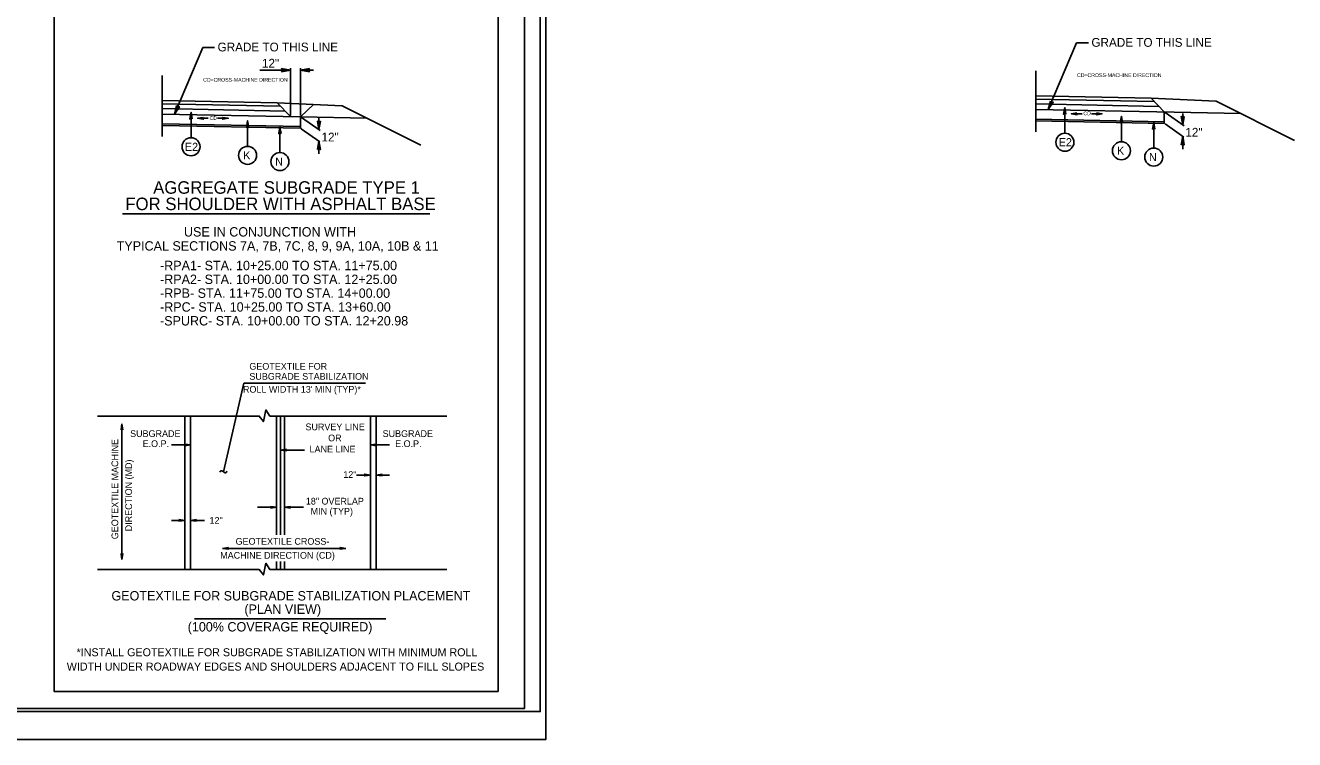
# Model space of a CAD drawing. Extents: x 573748 to 574632, y -54663 to -53209.
# Drawn here: x 574197.7 to 574400.7, y -54603.6 to -54489.5 of the extents above; entities that cross this region are included whole.
import ezdxf

# ---------------------------------------------------------------- set-up
doc = ezdxf.new("R2010")
doc.units = 0
for name, color, linetype in [('Prop Dimension', 7, 'Continuous'), ('Prop Dimension Text', 7, 'Continuous'), ('Prop Terminator CELL', 7, 'Continuous'), ('Sheet Cutting Line CELL', 7, 'Continuous'), ('Sheet Plot Border Inside CELL', 7, 'Continuous'), ('Sheet Plot Border Outside CELL', 7, 'Continuous'), ('Sheet Typical CELL', 7, 'Continuous'), ('Typical Hinge Slope Interstate CELL', 7, 'Continuous'), ('Typical ID Circle CELL', 7, 'Continuous'), ('Typical Pavement Slope CELL', 7, 'Continuous'), ('Typical Shoulder Slope CELL', 7, 'Continuous'), ('Typical Terminator CELL', 7, 'Continuous'), ('Typical Text General CELL', 7, 'Continuous'), ('Typical Text ID Circle CELL', 7, 'Continuous')]:
    doc.layers.add(name, color=color, linetype=linetype)

msp = doc.modelspace()

# ---------------------------------------------------------------- linework, layer by layer
at = {"layer": 'Prop Dimension'}
for p, q in [((574226.11, -54492.97), (574221.58, -54503.66)), ((574226.11, -54492.97), (574228, -54492.97)), ((574365.85, -54492.23), (574361.32, -54502.92)), ((574365.85, -54492.23), (574367.74, -54492.23)), ((574219.59, -54507.2), (574219.59, -54497.44)), ((574359.33, -54506.46), (574359.33, -54496.7)), ((574366.72, -54503.58), (574365.01, -54503.58)), ((574368.22, -54503.58), (574369.92, -54503.58)), ((574226.98, -54504.31), (574225.27, -54504.31)), ((574228.48, -54504.31), (574230.19, -54504.31)), ((574213.27, -54519.6), (574262.41, -54519.6))]:
    msp.add_line(p, q, dxfattribs=at)
msp.add_lwpolyline([(574202.34, -54435.95), (574273.34, -54435.95), (574273.34, -54595.94), (574202.34, -54595.94)], close=True, dxfattribs=at)
at = {"layer": 'Prop Dimension Text'}
for p, q in [((574235.21, -54496.62), (574240.14, -54496.62)), ((574240.14, -54503.87), (574240.14, -54496.3)), ((574241.74, -54503.87), (574241.74, -54496.3)), ((574241.74, -54496.62), (574243.8, -54496.62)), ((574380.02, -54503.4), (574383.03, -54505.51)), ((574382.82, -54505.36), (574382.82, -54503.54)), ((574241.89, -54504.17), (574244.9, -54506.27)), ((574244.68, -54506.12), (574244.68, -54504.31)), ((574379.99, -54505.2), (574382.99, -54507.3)), ((574241.85, -54505.97), (574244.85, -54508.07)), ((574382.82, -54509.24), (574382.82, -54507.18)), ((574244.68, -54510.01), (574244.68, -54507.95)), ((574229.41, -54560.83), (574232.67, -54546.68)), ((574232.67, -54546.68), (574252.15, -54546.68)), ((574223.23, -54551.93), (574223.23, -54576.45)), ((574224.15, -54551.93), (574224.15, -54576.45)), ((574237.89, -54570.9), (574237.89, -54551.93)), ((574238.53, -54570.9), (574238.53, -54551.93)), ((574239.17, -54570.9), (574239.17, -54551.93)), ((574252.91, -54551.93), (574252.91, -54576.45)), ((574253.83, -54551.93), (574253.83, -54576.45)), ((574213.19, -54553.15), (574213.05, -54554.12)), ((574213.05, -54554.12), (574213.19, -54554)), ((574213.07, -54554.1), (574213.19, -54553.15)), ((574213.19, -54553.15), (574213.09, -54554.08)), ((574213.11, -54554.07), (574213.19, -54553.15)), ((574213.19, -54553.15), (574213.13, -54554.05)), ((574213.15, -54554.03), (574213.19, -54553.15)), ((574213.19, -54553.15), (574213.17, -54554.01)), ((574213.19, -54553.15), (574213.32, -54554.12)), ((574213.19, -54554), (574213.19, -54553.15)), ((574213.2, -54554.01), (574213.19, -54553.15)), ((574213.19, -54553.15), (574213.22, -54554.03)), ((574213.24, -54554.05), (574213.19, -54553.15)), ((574213.19, -54553.15), (574213.26, -54554.07)), ((574213.28, -54554.08), (574213.19, -54553.15)), ((574213.19, -54553.15), (574213.3, -54554.1)), ((574213.19, -54574.87), (574213.19, -54553.15)), ((574213.19, -54554), (574213.32, -54554.12)), ((574221.1, -54556.52), (574224.15, -54556.52)), ((574224.15, -54556.52), (574223.18, -54556.39)), ((574223.18, -54556.39), (574223.31, -54556.52)), ((574224.15, -54556.52), (574223.18, -54556.65)), ((574223.31, -54556.52), (574223.18, -54556.65)), ((574223.2, -54556.4), (574224.15, -54556.52)), ((574224.15, -54556.52), (574223.2, -54556.63)), ((574224.15, -54556.52), (574223.22, -54556.42)), ((574223.22, -54556.61), (574224.15, -54556.52)), ((574223.23, -54556.44), (574224.15, -54556.52)), ((574224.15, -54556.52), (574223.23, -54556.59)), ((574224.15, -54556.52), (574223.25, -54556.46)), ((574223.25, -54556.57), (574224.15, -54556.52)), ((574223.27, -54556.48), (574224.15, -54556.52)), ((574224.15, -54556.52), (574223.27, -54556.55)), ((574224.15, -54556.52), (574223.29, -54556.5)), ((574223.29, -54556.54), (574224.15, -54556.52)), ((574223.31, -54556.52), (574224.15, -54556.52)), ((574252.91, -54556.52), (574253.88, -54556.39)), ((574253.87, -54556.4), (574252.91, -54556.52)), ((574252.91, -54556.52), (574253.85, -54556.42)), ((574253.83, -54556.44), (574252.91, -54556.52)), ((574252.91, -54556.52), (574253.81, -54556.46)), ((574253.79, -54556.48), (574252.91, -54556.52)), ((574252.91, -54556.52), (574253.78, -54556.5)), ((574255.96, -54556.52), (574252.91, -54556.52)), ((574252.91, -54556.52), (574253.88, -54556.65)), ((574253.76, -54556.52), (574252.91, -54556.52)), ((574253.78, -54556.54), (574252.91, -54556.52)), ((574252.91, -54556.52), (574253.79, -54556.55)), ((574253.81, -54556.57), (574252.91, -54556.52)), ((574252.91, -54556.52), (574253.83, -54556.59)), ((574253.85, -54556.61), (574252.91, -54556.52)), ((574252.91, -54556.52), (574253.87, -54556.63)), ((574253.88, -54556.39), (574253.76, -54556.52)), ((574253.76, -54556.52), (574253.88, -54556.65)), ((574238.53, -54557.36), (574239.5, -54557.23)), ((574238.53, -54557.36), (574239.48, -54557.25)), ((574239.46, -54557.26), (574238.53, -54557.36)), ((574238.53, -54557.36), (574239.45, -54557.28)), ((574239.43, -54557.3), (574238.53, -54557.36)), ((574238.53, -54557.36), (574239.41, -54557.32)), ((574239.39, -54557.34), (574238.53, -54557.36)), ((574238.53, -54557.36), (574239.5, -54557.49)), ((574239.48, -54557.47), (574238.53, -54557.36)), ((574238.53, -54557.36), (574239.46, -54557.45)), ((574239.45, -54557.43), (574238.53, -54557.36)), ((574238.53, -54557.36), (574239.43, -54557.41)), ((574239.41, -54557.4), (574238.53, -54557.36)), ((574238.53, -54557.36), (574239.39, -54557.38)), ((574239.38, -54557.36), (574238.53, -54557.36)), ((574238.53, -54557.36), (574242.38, -54557.36)), ((574239.38, -54557.36), (574239.5, -54557.23)), ((574239.5, -54557.49), (574239.38, -54557.36)), ((574228.82, -54560.89), (574228.87, -54560.8)), ((574229.24, -54560.71), (574229.58, -54560.95)), ((574229.91, -54560.87), (574229.97, -54560.75)), ((574252.91, -54561.34), (574250.67, -54561.34)), ((574252.91, -54561.34), (574251.94, -54561.21)), ((574252.07, -54561.34), (574251.94, -54561.21)), ((574252.91, -54561.34), (574251.94, -54561.47)), ((574251.94, -54561.47), (574252.07, -54561.34)), ((574252.91, -54561.34), (574251.96, -54561.23)), ((574251.96, -54561.45), (574252.91, -54561.34)), ((574251.98, -54561.25), (574252.91, -54561.34)), ((574252.91, -54561.34), (574251.98, -54561.44)), ((574252.91, -54561.34), (574252, -54561.27)), ((574252, -54561.42), (574252.91, -54561.34)), ((574252.02, -54561.29), (574252.91, -54561.34)), ((574252.91, -54561.34), (574252.02, -54561.4)), ((574252.91, -54561.34), (574252.03, -54561.31)), ((574252.03, -54561.38), (574252.91, -54561.34)), ((574252.05, -54561.32), (574252.91, -54561.34)), ((574252.91, -54561.34), (574252.05, -54561.36)), ((574252.07, -54561.34), (574252.91, -54561.34)), ((574253.83, -54561.34), (574254.8, -54561.21)), ((574254.78, -54561.23), (574253.83, -54561.34)), ((574253.83, -54561.34), (574254.76, -54561.25)), ((574254.74, -54561.27), (574253.83, -54561.34)), ((574253.83, -54561.34), (574254.73, -54561.29)), ((574254.71, -54561.3), (574253.83, -54561.34)), ((574253.83, -54561.34), (574254.69, -54561.32)), ((574255.96, -54561.34), (574253.83, -54561.34)), ((574253.83, -54561.34), (574254.8, -54561.47)), ((574254.67, -54561.34), (574253.83, -54561.34)), ((574254.69, -54561.36), (574253.83, -54561.34)), ((574253.83, -54561.34), (574254.71, -54561.38)), ((574254.73, -54561.4), (574253.83, -54561.34)), ((574253.83, -54561.34), (574254.74, -54561.42)), ((574254.76, -54561.44), (574253.83, -54561.34)), ((574253.83, -54561.34), (574254.78, -54561.45)), ((574254.8, -54561.21), (574254.67, -54561.34)), ((574254.67, -54561.34), (574254.8, -54561.47)), ((574234.87, -54566.5), (574237.89, -54566.5)), ((574237.89, -54566.5), (574236.92, -54566.37)), ((574236.92, -54566.37), (574237.05, -54566.5)), ((574237.89, -54566.5), (574236.92, -54566.63)), ((574237.05, -54566.5), (574236.92, -54566.63)), ((574236.94, -54566.39), (574237.89, -54566.5)), ((574237.89, -54566.5), (574236.94, -54566.61)), ((574237.89, -54566.5), (574236.96, -54566.41)), ((574236.96, -54566.59), (574237.89, -54566.5)), ((574236.98, -54566.43), (574237.89, -54566.5)), ((574237.89, -54566.5), (574236.98, -54566.58)), ((574237.89, -54566.5), (574236.99, -54566.45)), ((574236.99, -54566.56), (574237.89, -54566.5)), ((574237.01, -54566.46), (574237.89, -54566.5)), ((574237.89, -54566.5), (574237.01, -54566.54)), ((574237.89, -54566.5), (574237.03, -54566.48)), ((574237.03, -54566.52), (574237.89, -54566.5)), ((574237.05, -54566.5), (574237.89, -54566.5)), ((574239.17, -54566.5), (574240.14, -54566.37)), ((574239.17, -54566.5), (574240.12, -54566.39)), ((574240.1, -54566.41), (574239.17, -54566.5)), ((574239.17, -54566.5), (574240.09, -54566.43)), ((574240.07, -54566.45), (574239.17, -54566.5)), ((574239.17, -54566.5), (574240.05, -54566.46)), ((574240.03, -54566.48), (574239.17, -54566.5)), ((574239.17, -54566.5), (574240.14, -54566.63)), ((574240.12, -54566.61), (574239.17, -54566.5)), ((574239.17, -54566.5), (574240.1, -54566.59)), ((574240.09, -54566.58), (574239.17, -54566.5)), ((574239.17, -54566.5), (574240.07, -54566.56)), ((574240.05, -54566.54), (574239.17, -54566.5)), ((574239.17, -54566.5), (574240.03, -54566.52)), ((574240.02, -54566.5), (574239.17, -54566.5)), ((574242.2, -54566.5), (574239.17, -54566.5)), ((574240.02, -54566.5), (574240.14, -54566.37)), ((574240.14, -54566.63), (574240.02, -54566.5)), ((574221.1, -54568.6), (574223.23, -54568.6)), ((574223.23, -54568.6), (574222.27, -54568.47)), ((574222.27, -54568.47), (574222.39, -54568.6)), ((574223.23, -54568.6), (574222.27, -54568.73)), ((574222.39, -54568.6), (574222.27, -54568.73)), ((574222.28, -54568.49), (574223.23, -54568.6)), ((574223.23, -54568.6), (574222.28, -54568.72)), ((574223.23, -54568.6), (574222.3, -54568.51)), ((574222.3, -54568.7), (574223.23, -54568.6)), ((574222.32, -54568.53), (574223.23, -54568.6)), ((574223.23, -54568.6), (574222.32, -54568.68)), ((574223.23, -54568.6), (574222.34, -54568.55)), ((574222.34, -54568.66), (574223.23, -54568.6)), ((574222.35, -54568.57), (574223.23, -54568.6)), ((574223.23, -54568.6), (574222.35, -54568.64)), ((574223.23, -54568.6), (574222.37, -54568.59)), ((574222.37, -54568.62), (574223.23, -54568.6)), ((574222.39, -54568.6), (574223.23, -54568.6)), ((574224.15, -54568.6), (574225.12, -54568.47)), ((574224.15, -54568.6), (574225.1, -54568.49)), ((574225.08, -54568.51), (574224.15, -54568.6)), ((574224.15, -54568.6), (574225.06, -54568.53)), ((574225.05, -54568.55), (574224.15, -54568.6)), ((574224.15, -54568.6), (574225.03, -54568.57)), ((574225.01, -54568.59), (574224.15, -54568.6)), ((574224.15, -54568.6), (574226.4, -54568.6)), ((574224.15, -54568.6), (574225.12, -54568.74)), ((574225.1, -54568.72), (574224.15, -54568.6)), ((574224.15, -54568.6), (574225.08, -54568.7)), ((574225.06, -54568.68), (574224.15, -54568.6)), ((574224.15, -54568.6), (574225.05, -54568.66)), ((574225.03, -54568.64), (574224.15, -54568.6)), ((574224.15, -54568.6), (574225.01, -54568.62)), ((574224.99, -54568.6), (574224.15, -54568.6)), ((574224.99, -54568.6), (574225.12, -54568.47)), ((574225.12, -54568.74), (574224.99, -54568.6)), ((574213.19, -54574.87), (574213.06, -54573.9)), ((574213.19, -54574.02), (574213.06, -54573.9)), ((574213.19, -54574.87), (574213.07, -54573.92)), ((574213.09, -54573.94), (574213.19, -54574.87)), ((574213.19, -54574.87), (574213.11, -54573.95)), ((574213.13, -54573.97), (574213.19, -54574.87)), ((574213.19, -54574.87), (574213.15, -54573.99)), ((574213.17, -54574.01), (574213.19, -54574.87)), ((574213.19, -54574.87), (574213.32, -54573.9)), ((574213.32, -54573.9), (574213.19, -54574.02)), ((574213.3, -54573.92), (574213.19, -54574.87)), ((574213.19, -54574.87), (574213.28, -54573.94)), ((574213.26, -54573.95), (574213.19, -54574.87)), ((574213.19, -54574.87), (574213.24, -54573.97)), ((574213.22, -54573.99), (574213.19, -54574.87)), ((574213.19, -54574.87), (574213.21, -54574.01)), ((574213.19, -54574.02), (574213.19, -54574.87)), ((574229.24, -54573.07), (574230.21, -54572.94)), ((574229.24, -54573.07), (574230.2, -54572.95)), ((574230.18, -54572.97), (574229.24, -54573.07)), ((574229.24, -54573.07), (574230.16, -54572.99)), ((574230.14, -54573.01), (574229.24, -54573.07)), ((574229.24, -54573.07), (574230.13, -54573.03)), ((574230.11, -54573.05), (574229.24, -54573.07)), ((574229.24, -54573.07), (574230.21, -54573.2)), ((574230.2, -54573.18), (574229.24, -54573.07)), ((574229.24, -54573.07), (574230.18, -54573.16)), ((574230.16, -54573.14), (574229.24, -54573.07)), ((574229.24, -54573.07), (574230.14, -54573.12)), ((574230.13, -54573.1), (574229.24, -54573.07)), ((574229.24, -54573.07), (574230.11, -54573.09)), ((574230.09, -54573.07), (574229.24, -54573.07)), ((574229.24, -54573.07), (574249.01, -54573.07)), ((574230.09, -54573.07), (574230.21, -54572.94)), ((574230.21, -54573.2), (574230.09, -54573.07)), ((574249.01, -54573.07), (574248.05, -54572.94)), ((574248.05, -54572.94), (574248.17, -54573.07)), ((574249.01, -54573.07), (574248.05, -54573.2)), ((574248.17, -54573.07), (574248.05, -54573.2)), ((574248.06, -54572.95), (574249.01, -54573.07)), ((574249.01, -54573.07), (574248.06, -54573.18)), ((574249.01, -54573.07), (574248.08, -54572.97)), ((574248.08, -54573.16), (574249.01, -54573.07)), ((574248.1, -54572.99), (574249.01, -54573.07)), ((574249.01, -54573.07), (574248.1, -54573.14)), ((574249.01, -54573.07), (574248.12, -54573.01)), ((574248.12, -54573.12), (574249.01, -54573.07)), ((574248.13, -54573.03), (574249.01, -54573.07)), ((574249.01, -54573.07), (574248.13, -54573.1)), ((574249.01, -54573.07), (574248.15, -54573.05)), ((574248.15, -54573.09), (574249.01, -54573.07)), ((574248.17, -54573.07), (574249.01, -54573.07)), ((574237.89, -54576.45), (574237.89, -54575.15)), ((574238.53, -54576.45), (574238.53, -54575.15)), ((574239.17, -54576.45), (574239.17, -54575.15)), ((574224.78, -54584.34), (574255.37, -54584.34))]:
    msp.add_line(p, q, dxfattribs=at)
for points in [[(574265.16, -54551.93), (574236.84, -54551.93), (574236.2, -54550.93), (574235.8, -54552.8), (574235.15, -54551.93), (574209.29, -54551.93)], [(574265.16, -54576.45), (574236.84, -54576.45), (574236.2, -54575.45), (574235.8, -54577.32), (574235.15, -54576.45), (574209.29, -54576.45)]]:
    msp.add_lwpolyline(points, dxfattribs=at)
for centre, radius, start, end in [((574229.09, -54560.89), 0.234, 48.0321, 157.831), ((574229.71, -54560.8), 0.208, 230.477, 338.7625)]:
    msp.add_arc(centre, radius, start, end, dxfattribs=at)
at = {"layer": 'Prop Terminator CELL'}
for points in [[(574365.91, -54503.42), (574365.01, -54503.58), (574365.92, -54503.74), (574365.8, -54503.58)], [(574369.02, -54503.42), (574369.92, -54503.58), (574369.02, -54503.74), (574369.13, -54503.58)], [(574226.17, -54504.16), (574225.27, -54504.31), (574226.18, -54504.47), (574226.06, -54504.31)], [(574229.29, -54504.16), (574230.19, -54504.31), (574229.28, -54504.47), (574229.4, -54504.31)], [(574244.91, -54504.77), (574244.68, -54506.12), (574244.44, -54504.77), (574244.68, -54504.94)], [(574383.05, -54504.01), (574382.82, -54505.36), (574382.58, -54504), (574382.82, -54504.17)], [(574382.58, -54508.53), (574382.82, -54507.18), (574383.06, -54508.54), (574382.82, -54508.37)], [(574244.44, -54509.3), (574244.68, -54507.95), (574244.92, -54509.31), (574244.68, -54509.13)]]:
    msp.add_lwpolyline(points, close=True, dxfattribs=at)
at = {"layer": 'Sheet Cutting Line CELL'}
msp.add_line((573944.17, -54603.65), (574280.97, -54603.65), dxfattribs=at)
at = {"layer": 'Sheet Plot Border Inside CELL'}
msp.add_lwpolyline([(574280.07, -54388.14), (573946.77, -54388.14), (573946.77, -54599.16), (574280.07, -54599.16)], close=True, dxfattribs=at)
at = {"layer": 'Sheet Plot Border Outside CELL'}
msp.add_lwpolyline([(574280.97, -54383.65), (573944.17, -54383.65), (573944.17, -54603.65), (574280.97, -54603.65)], close=True, dxfattribs=at)
at = {"layer": 'Sheet Typical CELL'}
msp.add_lwpolyline([(574277.57, -54388.65), (573977.57, -54388.65), (573977.57, -54598.65), (574277.57, -54598.65)], close=True, dxfattribs=at)
at = {"layer": 'Typical Hinge Slope Interstate CELL'}
for p, q in [((574388.15, -54501.57), (574400.71, -54507.85)), ((574248.41, -54502.3), (574260.97, -54508.58))]:
    msp.add_line(p, q, dxfattribs=at)
for points in [[(574219.59, -54505.17), (574241.74, -54505.61), (574241.74, -54505.89), (574219.59, -54505.45)], [(574359.33, -54504.43), (574379.87, -54504.85), (574379.87, -54505.12), (574359.33, -54504.71)]]:
    msp.add_lwpolyline(points, close=True, dxfattribs=at)
at = {"layer": 'Typical ID Circle CELL'}
for p, q in [((574224.23, -54507.42), (574224.23, -54503.34)), ((574363.97, -54506.69), (574363.97, -54502.6)), ((574233.27, -54508.79), (574233.27, -54504.7)), ((574238.45, -54509.79), (574238.45, -54505.7)), ((574373.01, -54508.05), (574373.01, -54503.97)), ((574378.19, -54509.05), (574378.19, -54504.97))]:
    msp.add_line(p, q, dxfattribs=at)
for centre in [(574224.23, -54508.86), (574363.97, -54508.13), (574233.27, -54510.23), (574238.45, -54511.23), (574373.01, -54509.49), (574378.19, -54510.5)]:
    msp.add_circle(centre, 1.44, dxfattribs=at)
at = {"layer": 'Typical Pavement Slope CELL'}
for p, q in [((574238.01, -54501.82), (574219.59, -54501.45)), ((574378.27, -54501.63), (574359.32, -54501.25)), ((574377.75, -54501.09), (574359.33, -54500.72)), ((574239.28, -54503.14), (574219.56, -54502.75)), ((574238.53, -54502.36), (574219.58, -54501.98)), ((574241.74, -54504.06), (574219.59, -54503.62)), ((574379.02, -54502.41), (574359.3, -54502.01)), ((574381.47, -54503.33), (574359.33, -54502.88)), ((574241.74, -54505.61), (574219.59, -54505.17)), ((574379.87, -54504.85), (574359.33, -54504.44))]:
    msp.add_line(p, q, dxfattribs=at)
at = {"layer": 'Typical Shoulder Slope CELL'}
for p, q in [((574377.75, -54501.09), (574388.15, -54501.57)), ((574379.87, -54503.29), (574377.75, -54501.09)), ((574238.01, -54501.82), (574248.41, -54502.3)), ((574240.14, -54504.03), (574238.01, -54501.82)), ((574243.79, -54502.09), (574241.74, -54504.06)), ((574379.87, -54503.29), (574379.87, -54504.85)), ((574381.47, -54503.33), (574392.09, -54503.54)), ((574241.74, -54505.89), (574219.59, -54505.45)), ((574241.74, -54504.06), (574241.74, -54505.61)), ((574241.74, -54504.06), (574252.36, -54504.27)), ((574379.87, -54505.12), (574359.33, -54504.71))]:
    msp.add_line(p, q, dxfattribs=at)
at = {"layer": 'Typical Terminator CELL'}
for points in [[(574238.71, -54496.86), (574240.14, -54496.62), (574238.7, -54496.37), (574238.88, -54496.62)], [(574243.16, -54496.37), (574241.74, -54496.62), (574243.17, -54496.87), (574242.99, -54496.62)], [(574361.65, -54501.54), (574361.32, -54502.92), (574362.11, -54501.73), (574361.81, -54501.79)], [(574221.91, -54502.27), (574221.58, -54503.66), (574222.37, -54502.46), (574222.07, -54502.53)], [(574224.41, -54504.39), (574224.23, -54503.34), (574224.04, -54504.4), (574224.23, -54504.26)], [(574364.15, -54503.66), (574363.97, -54502.6), (574363.78, -54503.66), (574363.97, -54503.53)], [(574233.45, -54505.76), (574233.27, -54504.7), (574233.08, -54505.76), (574233.27, -54505.63)], [(574238.63, -54506.76), (574238.45, -54505.7), (574238.27, -54506.76), (574238.45, -54506.63)], [(574373.19, -54505.02), (574373.01, -54503.97), (574372.82, -54505.03), (574373.01, -54504.89)], [(574378.37, -54506.02), (574378.19, -54504.97), (574378, -54506.03), (574378.19, -54505.89)]]:
    msp.add_lwpolyline(points, close=True, dxfattribs=at)

# ---------------------------------------------------------------- texts
at = {"layer": 'Prop Dimension Text'}
for s, height, p in [('12"', 1.4, (574235.57, -54496.2)), ('12"', 1.4, (574245.1, -54508.01)), ('12"', 1.4, (574383.24, -54507.24)), ('GEOTEXTILE FOR', 1.0729, (574233.56, -54544.5)), ('SUBGRADE STABILIZATION', 1.0729, (574233.56, -54546.11)), ("ROLL WIDTH 13' MIN (TYP)*", 1.0729, (574232.54, -54548.18)), ('SUBGRADE', 1.073, (574214.49, -54555.26)), ('SURVEY LINE', 1.0729, (574242.53, -54554.18)), ('SUBGRADE', 1.073, (574254.87, -54555.26)), ('E.O.P.', 1.073, (574216.49, -54556.87)), ('OR', 1.073, (574246.16, -54555.95)), ('E.O.P.', 1.073, (574256.87, -54556.87)), ('LANE LINE', 1.073, (574243.19, -54557.74)), ('12"', 1.073, (574248.58, -54561.8)), ('18" OVERLAP', 1.0729, (574242.59, -54566.06)), ('MIN (TYP)', 1.073, (574243.35, -54567.67)), ('12"', 1.073, (574227.19, -54569.13))]:
    msp.add_text(s, height=height, dxfattribs=at).set_placement(p)
for s, height, rotation, p in [('GEOTEXTILE MACHINE', 1.0729, 90, (574212.59, -54571.61)), ('DIRECTION (MD)', 1.0729, 90, (574214.79, -54570.34)), ('GEOTEXTILE CROSS-', 1.0729, 360, (574231.36, -54572.49)), ('MACHINE DIRECTION (CD)', 1.0729, 360, (574228.9, -54574.72)), ('GEOTEXTILE FOR SUBGRADE STABILIZATION PLACEMENT', 1.5, 360, (574211.51, -54581.4)), ('(PLAN VIEW)', 1.5, 360, (574232.77, -54583.54)), ('(100% COVERAGE REQUIRED)', 1.5, 360, (574223.7, -54586.36)), ('*INSTALL GEOTEXTILE FOR SUBGRADE STABILIZATION WITH MINIMUM ROLL', 1.28, 360, (574205.93, -54590.32)), ('WIDTH UNDER ROADWAY EDGES AND SHOULDERS ADJACENT TO FILL SLOPES', 1.28, 360, (574204.36, -54592.61))]:
    msp.add_text(s, height=height, rotation=rotation, dxfattribs=at).set_placement(p)
at = {"layer": 'Typical Hinge Slope Interstate CELL'}
for s, p in [('CD=CROSS-MACHINE DIRECTION', (574365.91, -54497.71)), ('CD=CROSS-MACHINE DIRECTION', (574226.17, -54498.45)), ('CD', (574366.93, -54503.82)), ('CD', (574227.19, -54504.56))]:
    msp.add_text(s, height=0.6, dxfattribs=at).set_placement(p)
at = {"layer": 'Typical Text General CELL'}
for s, height, p in [('GRADE TO THIS LINE', 1.4, (574368.22, -54492.87)), ('GRADE TO THIS LINE', 1.4, (574228.48, -54493.61)), ('AGGREGATE SUBGRADE TYPE 1', 2, (574218.18, -54516.37)), ('FOR SHOULDER WITH ASPHALT BASE', 2, (574213.73, -54518.99)), ('USE IN CONJUNCTION WITH', 1.5, (574223.1, -54523.21)), ('TYPICAL SECTIONS 7A, 7B, 7C, 8, 9, 9A, 10A, 10B & 11', 1.5, (574212.34, -54525.46)), ('-RPA1- STA. 10+25.00 TO STA. 11+75.00', 1.5, (574219.27, -54528.59)), ('-RPA2- STA. 10+00.00 TO STA. 12+25.00', 1.5, (574219.27, -54530.8)), ('-RPB- STA. 11+75.00 TO STA. 14+00.00', 1.5, (574219.27, -54533.01)), ('-RPC- STA. 10+25.00 TO STA. 13+60.00', 1.5, (574219.27, -54535.22)), ('-SPURC- STA. 10+00.00 TO STA. 12+20.98', 1.5, (574219.27, -54537.43))]:
    msp.add_text(s, height=height, dxfattribs=at).set_placement(p)
at = {"layer": 'Typical Text ID Circle CELL'}
for s, height, p in [('E2', 1.291, (574362.99, -54508.77)), ('E2', 1.291, (574223.25, -54509.51)), ('K', 1.29, (574232.58, -54510.87)), ('K', 1.29, (574372.31, -54510.14)), ('N', 1.29, (574377.42, -54511.14)), ('N', 1.29, (574237.68, -54511.87))]:
    msp.add_text(s, height=height, dxfattribs=at).set_placement(p)

doc.saveas('drawing.dxf')
